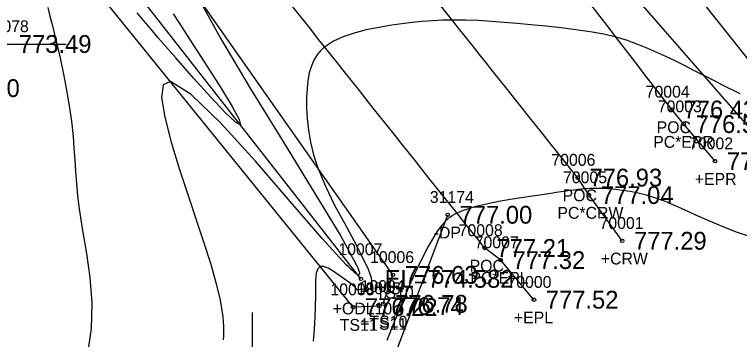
# Model space of a CAD drawing. Extents: x 1376587 to 1378239, y 1000335 to 1003031.
# Drawn here: x 1378121.7 to 1378182.9, y 1000373.4 to 1000400.9 of the extents above; entities that cross this region are included whole.
import ezdxf

# ---------------------------------------------------------------- set-up
doc = ezdxf.new("R2010")
doc.units = 0
for name, color, linetype in [('RD_DTM_BkLn1', 7, 'Continuous'), ('RD_DTM_BkLn2', 7, 'Continuous'), ('RD_DTM_BkLn_txCode', 7, 'Continuous'), ('RD_DTM_Major1', 7, 'Continuous'), ('RD_DTM_Minor1', 7, 'Continuous'), ('RD_EX_Driveway', 7, 'Continuous'), ('RD_EX_Driveway_txCode', 7, 'Continuous'), ('RD_EX_H2O', 7, 'Continuous'), ('RD_EX_H2O_txCode', 7, 'Continuous'), ('RD_EX_Misc', 7, 'Continuous'), ('RD_EX_Misc_txCode', 7, 'Continuous'), ('RD_EX_Road', 7, 'Continuous'), ('RD_EX_Road_txCode', 7, 'Continuous'), ('RD_EX_TX_Driveway_ELEV', 7, 'Continuous'), ('RD_EX_TX_H2O_ELEV', 7, 'Continuous'), ('RD_EX_TX_Misc_ELEV', 7, 'Continuous'), ('RD_EX_TX_Road_ELEV', 7, 'Continuous'), ('RD_HC_Survey_ELEV', 7, 'Continuous'), ('RD_HC_Survey_txCode', 7, 'Continuous'), ('RD_SMD_Locator', 7, 'Continuous')]:
    doc.layers.add(name, color=color, linetype=linetype)

msp = doc.modelspace()

# ---------------------------------------------------------------- linework, layer by layer
at = {"layer": 'RD_DTM_BkLn1'}
msp.add_lwpolyline([(1378172.971, 1000381.768), (1378170.173, 1000385.626), (1378169.212, 1000387.103)], dxfattribs=at)
msp.add_spline([(1378169.212, 1000387.103), (1378131.506, 1000434.744), (1378095.477, 1000481.988), (1378063.033, 1000526.867), (1378030.177, 1000574.233), (1377998.011, 1000622.539), (1377965.721, 1000673.201), (1377936, 1000721.493), (1377904.113, 1000773.429), (1377890.868, 1000795.129)], degree=3, dxfattribs=at)
at = {"layer": 'RD_DTM_BkLn2'}
for points in [[(1378152.795, 1000376.442), (1378153.623, 1000378.891), (1378133.341, 1000407.77), (1378106.208, 1000444.47), (1378079.422, 1000481.908), (1378052.603, 1000518.078), (1378027.38, 1000556.138), (1377999.887, 1000593.901), (1377975.443, 1000634.683), (1377966.188, 1000647.973)], [(1378152.458, 1000376.254), (1378150.255, 1000376.168), (1378128.245, 1000403.35), (1378101.014, 1000439.163), (1378072.773, 1000477.242), (1378039.24, 1000510.344), (1378015.855, 1000547.194), (1377989.301, 1000588.148), (1377962.727, 1000626.954), (1377952.76, 1000642.197)], [(1378184.932, 1000389.914), (1378162.528, 1000415.61), (1378132.296, 1000454.253), (1378102.474, 1000500.023), (1378076.88, 1000534.536), (1378051.356, 1000571.753), (1378025.282, 1000608.511), (1378019.607, 1000621.768)]]:
    msp.add_lwpolyline(points, dxfattribs=at)
at = {"layer": 'RD_DTM_Major1'}
msp.add_lwpolyline([(1378137.237, 1000402.223), (1378139.096, 1000398.804), (1378141.598, 1000394.592), (1378144.369, 1000390.083), (1378147.035, 1000385.77), (1378149.221, 1000382.145), (1378150.554, 1000379.704), (1378150.649, 1000379.49), (1378150.721, 1000379.308), (1378150.769, 1000379.158), (1378150.794, 1000379.041), (1378150.795, 1000378.956), (1378150.772, 1000378.905), (1378150.756, 1000378.895), (1378150.737, 1000378.889), (1378150.715, 1000378.889), (1378150.689, 1000378.893), (1378150.66, 1000378.902), (1378150.626, 1000378.916), (1378150.524, 1000378.975), (1378150.398, 1000379.067), (1378150.249, 1000379.191), (1378150.078, 1000379.347), (1378149.884, 1000379.534), (1378149.668, 1000379.751), (1378147.656, 1000381.971), (1378144.982, 1000385.067), (1378142.005, 1000388.488), (1378139.082, 1000391.686), (1378136.571, 1000394.111), (1378134.832, 1000395.215), (1378134.216, 1000394.943), (1378134.09, 1000393.875), (1378134.348, 1000392.2), (1378134.886, 1000390.106), (1378135.599, 1000387.781), (1378136.382, 1000385.414), (1378137.045, 1000383.453), (1378137.662, 1000381.603), (1378138.211, 1000379.866), (1378138.672, 1000378.245), (1378139.024, 1000376.741), (1378139.247, 1000375.356), (1378139.287, 1000374.948), (1378139.311, 1000374.55), (1378139.32, 1000374.16), (1378139.313, 1000373.775), (1378139.288, 1000373.394)], dxfattribs=at)
at = {"layer": 'RD_DTM_Minor1'}
for points in [[(1378124.471, 1000401.47), (1378124.66, 1000400.74), (1378124.844, 1000400.022), (1378125.023, 1000399.312), (1378125.196, 1000398.61), (1378125.52, 1000397.215), (1378125.812, 1000395.844), (1378126.07, 1000394.495), (1378126.29, 1000393.168), (1378126.472, 1000391.861), (1378126.611, 1000390.572), (1378126.691, 1000389.589), (1378126.758, 1000388.606), (1378126.822, 1000387.613), (1378126.898, 1000386.6), (1378126.996, 1000385.556), (1378127.129, 1000384.472), (1378127.421, 1000382.648), (1378127.75, 1000380.708), (1378128.036, 1000378.667), (1378128.195, 1000376.54), (1378128.145, 1000374.339), (1378127.806, 1000372.08)], [(1378135.065, 1000400.941), (1378135.54, 1000400.205), (1378136.762, 1000398.323), (1378138.001, 1000396.404), (1378139.139, 1000394.609), (1378140.056, 1000393.094), (1378140.632, 1000392.02), (1378140.749, 1000391.545), (1378140.329, 1000391.772), (1378139.454, 1000392.601), (1378138.243, 1000393.882), (1378136.814, 1000395.464), (1378135.286, 1000397.2), (1378133.778, 1000398.938), (1378133.167, 1000399.648), (1378132.579, 1000400.334), (1378132.011, 1000400.998)], [(1378182.94, 1000394.162), (1378182.421, 1000394.414), (1378181.902, 1000394.674), (1378181.386, 1000394.938), (1378180.872, 1000395.205), (1378180.363, 1000395.471), (1378179.858, 1000395.733), (1378179.033, 1000396.156), (1378178.225, 1000396.561), (1378177.432, 1000396.948), (1378176.653, 1000397.316), (1378175.888, 1000397.666), (1378175.136, 1000397.997), (1378174.712, 1000398.177), (1378174.286, 1000398.35), (1378173.854, 1000398.515), (1378173.408, 1000398.671), (1378172.945, 1000398.819), (1378172.458, 1000398.957), (1378171.414, 1000399.199), (1378170.278, 1000399.407), (1378169.071, 1000399.584), (1378167.816, 1000399.739), (1378166.535, 1000399.877), (1378165.247, 1000400.004), (1378164.12, 1000400.111), (1378163.005, 1000400.209), (1378161.904, 1000400.292), (1378160.817, 1000400.356), (1378159.743, 1000400.396), (1378158.683, 1000400.406), (1378157.81, 1000400.388), (1378156.945, 1000400.347), (1378156.085, 1000400.283), (1378155.228, 1000400.198), (1378154.372, 1000400.094), (1378153.515, 1000399.97), (1378152.431, 1000399.786), (1378151.369, 1000399.566), (1378150.359, 1000399.303), (1378149.426, 1000398.989), (1378148.601, 1000398.616), (1378147.911, 1000398.179), (1378147.793, 1000398.083), (1378147.681, 1000397.985), (1378147.574, 1000397.883), (1378147.474, 1000397.779), (1378147.379, 1000397.671), (1378147.289, 1000397.56), (1378146.974, 1000397.071), (1378146.734, 1000396.528), (1378146.559, 1000395.934), (1378146.439, 1000395.293), (1378146.366, 1000394.608), (1378146.33, 1000393.882), (1378146.326, 1000393.005), (1378146.371, 1000392.081), (1378146.476, 1000391.11), (1378146.654, 1000390.093), (1378146.917, 1000389.031), (1378147.277, 1000387.926), (1378147.925, 1000386.368), (1378148.698, 1000384.788), (1378149.52, 1000383.242), (1378150.315, 1000381.785), (1378151.006, 1000380.475), (1378151.517, 1000379.366), (1378151.655, 1000378.99), (1378151.791, 1000378.638), (1378151.809, 1000378.367), (1378151.826, 1000378.123), (1378151.802, 1000377.926), (1378151.739, 1000377.777), (1378151.705, 1000377.733), (1378151.665, 1000377.696), (1378151.62, 1000377.666), (1378151.57, 1000377.643), (1378151.514, 1000377.627), (1378151.454, 1000377.618), (1378151.273, 1000377.623), (1378151.063, 1000377.671), (1378150.859, 1000377.655), (1378150.642, 1000377.589), (1378150.311, 1000377.947), (1378150.004, 1000378.204), (1378149.525, 1000378.53), (1378149.041, 1000378.875), (1378148.572, 1000379.196), (1378148.141, 1000379.452), (1378147.768, 1000379.602), (1378147.474, 1000379.603), (1378147.264, 1000379.41), (1378147.142, 1000379.033), (1378147.085, 1000378.501), (1378147.069, 1000377.842), (1378147.07, 1000377.084), (1378147.065, 1000376.255), (1378147.031, 1000375.307), (1378146.966, 1000374.314), (1378146.871, 1000373.282)], [(1378183.56, 1000382.174), (1378182.543, 1000382.524), (1378181.49, 1000382.938), (1378180.428, 1000383.391), (1378179.385, 1000383.858), (1378178.05, 1000384.467), (1378177.721, 1000384.615), (1378177.398, 1000384.758), (1378177.079, 1000384.894), (1378176.764, 1000385.023), (1378176.452, 1000385.145), (1378175.729, 1000385.396), (1378175.017, 1000385.606), (1378174.322, 1000385.779), (1378173.65, 1000385.916), (1378173.009, 1000386.022), (1378172.403, 1000386.1), (1378172.17, 1000386.124), (1378171.944, 1000386.144), (1378171.723, 1000386.161), (1378171.507, 1000386.173), (1378171.296, 1000386.182), (1378171.088, 1000386.188), (1378170.878, 1000386.19), (1378170.669, 1000386.189), (1378170.462, 1000386.185), (1378170.254, 1000386.177), (1378170.044, 1000386.165), (1378169.832, 1000386.15), (1378169.537, 1000386.123), (1378169.232, 1000386.091), (1378168.918, 1000386.053), (1378168.592, 1000386.011), (1378168.253, 1000385.964), (1378167.394, 1000385.838), (1378167.129, 1000385.799), (1378166.576, 1000385.717), (1378165.399, 1000385.541), (1378164.462, 1000385.398), (1378163.504, 1000385.243), (1378162.552, 1000385.074), (1378161.631, 1000384.89), (1378160.77, 1000384.69), (1378160.443, 1000384.605), (1378160.132, 1000384.515), (1378159.835, 1000384.421), (1378159.553, 1000384.322), (1378159.287, 1000384.216), (1378159.037, 1000384.104), (1378158.839, 1000384.002), (1378158.65, 1000383.893), (1378158.469, 1000383.773), (1378158.295, 1000383.64), (1378158.124, 1000383.492), (1378157.956, 1000383.325), (1378157.902, 1000383.268), (1378157.849, 1000383.209), (1378157.796, 1000383.147), (1378157.742, 1000383.084), (1378157.635, 1000382.95), (1378157.536, 1000382.82), (1378157.486, 1000382.752), (1378157.437, 1000382.682), (1378157.386, 1000382.61), (1378157.336, 1000382.536), (1378156.61, 1000381.329), (1378155.854, 1000379.85), (1378155.097, 1000378.206), (1378154.367, 1000376.504), (1378153.695, 1000374.85), (1378153.109, 1000373.352)]]:
    msp.add_lwpolyline(points, dxfattribs=at)
at = {"layer": 'RD_EX_Driveway'}
msp.add_lwpolyline([(1378148.016, 1000354.029), (1378152.548, 1000368.828), (1378158.245, 1000383.963)], dxfattribs=at)
at = {"layer": 'RD_EX_H2O'}
for points in [[(1378150.92, 1000378.554), (1378129.931, 1000405.361), (1378103.429, 1000442.377), (1378075.971, 1000479.612), (1378048.045, 1000515.879), (1378023.997, 1000553.212), (1377996.392, 1000591.758), (1377970.527, 1000631.657), (1377963.482, 1000646.08)], [(1378187.963, 1000391.619), (1378166.952, 1000418.069), (1378136.831, 1000457.58), (1378104.578, 1000501.856), (1378079.015, 1000536.042), (1378053.898, 1000573.861), (1378029.308, 1000608.167), (1378022.926, 1000618.73)]]:
    msp.add_lwpolyline(points, dxfattribs=at)
at = {"layer": 'RD_EX_Misc'}
for p, q in [((1378116.032, 1000398.38), (1378126.032, 1000398.38)), ((1378141.759, 1000365.7), (1378141.759, 1000375.7))]:
    msp.add_line(p, q, dxfattribs=at)
at = {"layer": 'RD_EX_Road'}
for points in [[(1378180.814, 1000388.488), (1378178.174, 1000391.616), (1378177.15, 1000392.854)], [(1378165.519, 1000376.794), (1378162.716, 1000380.14), (1378161.362, 1000381.162)]]:
    msp.add_lwpolyline(points, dxfattribs=at)
for points in [[(1378177.15, 1000392.854), (1378139.733, 1000441.521), (1378104.671, 1000487.69), (1378071.786, 1000533.085), (1378038.454, 1000579.804), (1378007.554, 1000627.96), (1377974.27, 1000678.859), (1377944.465, 1000727.117), (1377913.028, 1000778.581), (1377899.668, 1000800.294)], [(1378161.362, 1000381.162), (1378123.914, 1000428.538), (1378087.578, 1000476.324), (1378055.075, 1000520.944), (1378021.673, 1000568.713), (1377989.952, 1000617.081), (1377957.327, 1000668.378), (1377927.534, 1000716.552), (1377895.409, 1000768.824), (1377883.752, 1000788.501)]]:
    msp.add_spline(points, degree=3, dxfattribs=at)
at = {"layer": 'RD_SMD_Locator'}
for centre in [(1378177.15, 1000392.854), (1378178.174, 1000391.616), (1378180.814, 1000388.488), (1378169.212, 1000387.103), (1378170.173, 1000385.626), (1378158.245, 1000383.963), (1378172.971, 1000381.768), (1378161.362, 1000381.162), (1378162.716, 1000380.14), (1378150.92, 1000378.554), (1378153.623, 1000378.891), (1378165.519, 1000376.794), (1378150.255, 1000376.168), (1378152.458, 1000376.254), (1378152.795, 1000376.442)]:
    msp.add_circle(centre, 0.15, dxfattribs=at)

# ---------------------------------------------------------------- texts
at = {"layer": 'RD_DTM_BkLn_txCode'}
for s, p in [('10006', (1378151.686, 1000379.891)), ('10008', (1378148.342, 1000377.168)), ('10005', (1378150.545, 1000377.254)), ('10004', (1378150.882, 1000377.442)), ('TS10', (1378152.174, 1000376.891)), ('+TS10', (1378150.858, 1000374.442)), ('TS11', (1378149.129, 1000374.168)), ('+TS11', (1378150.844, 1000374.254))]:
    msp.add_text(s, height=1, dxfattribs=at).set_placement(p)
at = {"layer": 'RD_EX_Driveway_txCode'}
for s, p in [('31174', (1378156.733, 1000384.963)), ('-DP', (1378157.056, 1000381.963))]:
    msp.add_text(s, height=1, dxfattribs=at).set_placement(p)
at = {"layer": 'RD_EX_H2O_txCode'}
for s, p in [('10007', (1378149.007, 1000380.554)), ('+ODL10', (1378148.534, 1000375.554))]:
    msp.add_text(s, height=1, dxfattribs=at).set_placement(p)
at = {"layer": 'RD_EX_Misc_txCode'}
msp.add_text('10078', height=1, dxfattribs=at).set_placement((1378119.158, 1000399.38))
at = {"layer": 'RD_EX_Road_txCode'}
for s, p in [('70004', (1378174.953, 1000393.854)), ('70003', (1378175.977, 1000392.616)), ('POC', (1378175.882, 1000390.854)), ('PC*EPR', (1378175.591, 1000389.616)), ('70002', (1378178.617, 1000389.488)), ('+EPR', (1378179.097, 1000386.488)), ('70008', (1378159.165, 1000382.162)), ('70007', (1378160.519, 1000381.14)), ('POC', (1378160.094, 1000379.162)), ('PC*EPL', (1378160.157, 1000378.14)), ('70000', (1378163.283, 1000377.794)), ('+EPL', (1378163.826, 1000374.794))]:
    msp.add_text(s, height=1, dxfattribs=at).set_placement(p)
at = {"layer": 'RD_EX_TX_Driveway_ELEV'}
msp.add_text('777.00', height=1.5, dxfattribs=at).set_placement((1378159.245, 1000383.213))
at = {"layer": 'RD_EX_TX_H2O_ELEV'}
msp.add_text('EL=774.582', height=1.5, dxfattribs=at).set_placement((1378152.92, 1000377.804))
at = {"layer": 'RD_EX_TX_Misc_ELEV'}
for s, p in [('773.49', (1378122.032, 1000397.63)), ('773.20', (1378115.978, 1000393.904)), ('776.63', (1378154.623, 1000378.141)), ('776.22', (1378151.255, 1000375.418)), ('776.74', (1378153.458, 1000375.504)), ('776.78', (1378153.795, 1000375.692))]:
    msp.add_text(s, height=1.5, dxfattribs=at).set_placement(p)
at = {"layer": 'RD_EX_TX_Road_ELEV'}
for s, p in [('776.43', (1378178.15, 1000392.104)), ('776.55', (1378179.174, 1000390.866)), ('776.77', (1378181.814, 1000387.738)), ('777.21', (1378162.362, 1000380.412)), ('777.32', (1378163.716, 1000379.39)), ('777.52', (1378166.519, 1000376.044))]:
    msp.add_text(s, height=1.5, dxfattribs=at).set_placement(p)
at = {"layer": 'RD_HC_Survey_ELEV'}
for s, p in [('776.93', (1378170.212, 1000386.353)), ('777.04', (1378171.173, 1000384.876)), ('777.29', (1378173.971, 1000381.018))]:
    msp.add_text(s, height=1.5, dxfattribs=at).set_placement(p)
at = {"layer": 'RD_HC_Survey_txCode'}
for s, p in [('70006', (1378166.992, 1000388.103)), ('70005', (1378167.976, 1000386.626)), ('POC', (1378167.944, 1000385.103)), ('PC*CRW', (1378167.504, 1000383.626)), ('70001', (1378171.058, 1000382.768)), ('+CRW', (1378171.168, 1000379.768))]:
    msp.add_text(s, height=1, dxfattribs=at).set_placement(p)

doc.saveas('drawing.dxf')
